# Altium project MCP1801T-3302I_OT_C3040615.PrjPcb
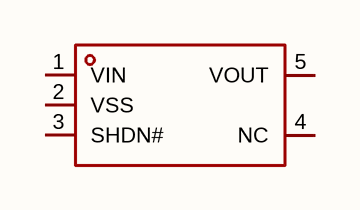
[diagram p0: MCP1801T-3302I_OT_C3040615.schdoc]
1 sheet, 1 parts. Net scope: global (net labels, ports and power ports of the same name join across sheets).

## Sheet MCP1801T-3302I_OT_C3040615.schdoc
size 127 x 101 mm

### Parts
U?  mcp1801t-3302i/ot  [SOT-23-5_L2.9-W1.6-P0.95-LS2.8-BL]  (value not drawn)

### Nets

Not connected (* = marked no-connect by the designer): U? 1(VIN) 2(VSS) 3(SHDN#) 4(NC) 5(VOUT)

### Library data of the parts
U? = mcp1801t-3302i/ot: 输出极性:正极;工作电压:10V;输出电压:3.3V;输出电流:150mA;电源纹波抑制比(PSRR):70dB@(10kHz);输出类型:固定;; Manufacturer: TECH PUBLIC(台舟); Symbol: MCP1801T-3302I/OT_C3040615; AddInBom: yes; ModelId: 018c57e721114987ae90467fe9f1d259; ModelTransform: 114.96,110.236,0,0,0,0,0,0,0; Output Configuration: 正极; Voltage - Supply: 10V; Output Voltage: 3.3V; Output Current: 150mA; Voltage Dropout: 200mV@(100mA); standby current: 25uA; Output Type: 固定; Number of Outputs: 1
